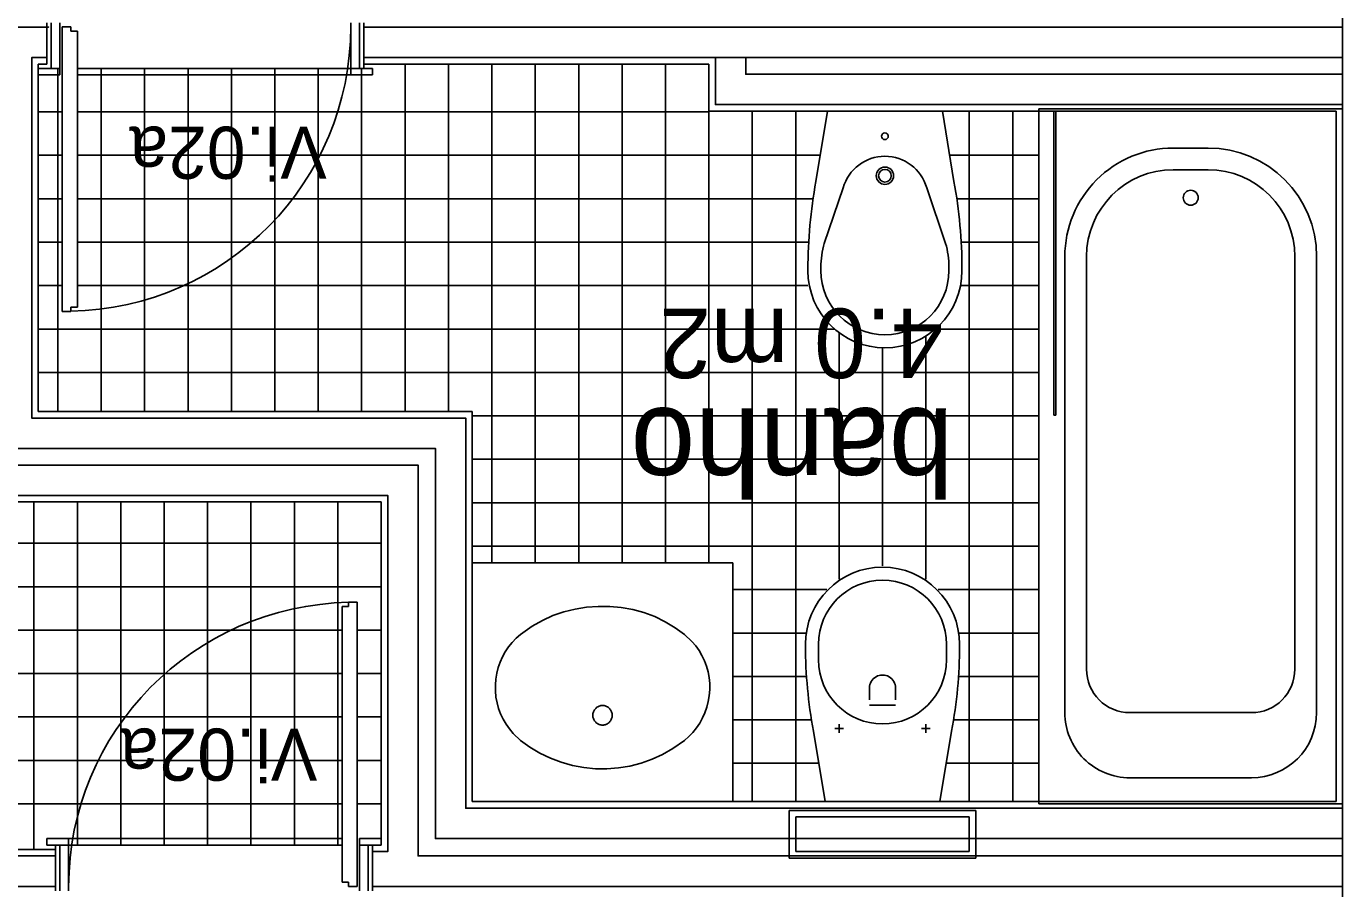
# Model space of a CAD drawing. Extents: x 1278 to 1356, y -253.7 to -224.
# Drawn here: x 1326.169 to 1329.202, y -240.419 to -238.434 of the extents above; entities that cross this region are included whole.
import ezdxf

# ---------------------------------------------------------------- set-up
doc = ezdxf.new("R2010")
doc.units = 0
for name, color, linetype in [('Level 1', 7, 'Continuous'), ('Level 10', 7, 'Continuous'), ('Level 11', 7, 'Continuous'), ('Level 13', 7, 'Continuous'), ('Level 2', 7, 'Continuous'), ('Level 36', 7, 'Continuous'), ('Level 4', 7, 'Continuous'), ('Level 40', 7, 'Continuous'), ('Level 60', 7, 'Continuous'), ('Level 65', 7, 'Continuous'), ('Level 66', 7, 'Continuous'), ('Level 67', 7, 'Continuous')]:
    doc.layers.add(name, color=color, linetype=linetype)

msp = doc.modelspace()

# ---------------------------------------------------------------- linework, layer by layer
at = {"layer": 'Level 1'}
for p, q in [((1326.2168, -238.5207), (1326.2168, -238.4257)), ((1326.9468, -238.5307), (1326.9468, -238.4257)), ((1326.2168, -238.4357), (1326.1318, -238.4357)), ((1329.2018, -238.4357), (1326.9468, -238.4357)), ((1326.1818, -239.3357), (1326.1818, -238.5057)), ((1326.1818, -238.5057), (1326.2168, -238.5057)), ((1327.7568, -238.5057), (1326.9468, -238.5057)), ((1329.2018, -238.5057), (1327.8268, -238.5057)), ((1327.1818, -239.3357), (1326.1818, -239.3357)), ((1327.1818, -240.234), (1327.1818, -239.3357)), ((1327.1118, -239.4057), (1326.1118, -239.4057)), ((1327.1118, -240.304), (1327.1118, -239.4057)), ((1326.0718, -239.444), (1327.0718, -239.444)), ((1327.0718, -239.444), (1327.0718, -240.344)), ((1326.0018, -239.514), (1327.0018, -239.514)), ((1327.0018, -239.514), (1327.0018, -240.334)), ((1326.2368, -240.319), (1326.2368, -240.424)), ((1326.9668, -240.319), (1326.9668, -240.424)), ((1327.0018, -240.334), (1326.9668, -240.334)), ((1327.0718, -240.344), (1329.2018, -240.344)), ((1326.1268, -240.414), (1326.2368, -240.414)), ((1326.9668, -240.414), (1329.2018, -240.414)), ((1329.2018, -240.414), (1329.2018, -242.034))]:
    msp.add_line(p, q, dxfattribs=at)
at = {"layer": 'Level 10'}
for p, q in [((1326.2418, -238.5307), (1326.2418, -239.3207)), ((1326.9168, -238.5307), (1326.2868, -238.5307)), ((1326.3418, -238.5307), (1326.3418, -239.3207)), ((1326.4418, -238.5307), (1326.4418, -239.3207)), ((1326.5418, -238.5307), (1326.5418, -239.3207)), ((1326.6418, -238.5307), (1326.6418, -239.3207)), ((1326.7418, -238.5307), (1326.7418, -239.3207)), ((1326.8418, -238.5307), (1326.8418, -239.3207)), ((1326.9418, -238.5307), (1326.9418, -239.3207)), ((1327.0418, -238.5207), (1327.0418, -239.3207)), ((1327.1418, -238.5207), (1327.1418, -239.3207)), ((1327.2418, -238.5207), (1327.2418, -239.669)), ((1327.3418, -238.5207), (1327.3418, -239.669)), ((1327.4418, -238.5207), (1327.4418, -239.669)), ((1327.5418, -238.5207), (1327.5418, -239.669)), ((1327.6418, -238.5207), (1327.6418, -239.669)), ((1326.1968, -238.6307), (1326.2518, -238.6307)), ((1326.2868, -238.6307), (1327.7418, -238.6307)), ((1327.7418, -238.629), (1327.7418, -239.669)), ((1327.8418, -238.629), (1327.8418, -240.219)), ((1327.9418, -238.629), (1327.9418, -240.219)), ((1328.3418, -238.629), (1328.3418, -240.219)), ((1328.4418, -238.629), (1328.4418, -240.219)), ((1326.1968, -238.7307), (1326.2518, -238.7307)), ((1326.2868, -238.7307), (1327.9984, -238.7307)), ((1328.2965, -238.7307), (1328.5018, -238.7307)), ((1326.1968, -238.8307), (1326.2518, -238.8307)), ((1326.2868, -238.8307), (1327.9819, -238.8307)), ((1328.313, -238.8307), (1328.5018, -238.8307)), ((1326.1968, -238.9307), (1326.2518, -238.9307)), ((1326.2868, -238.9307), (1327.9717, -238.9307)), ((1328.3232, -238.9307), (1328.5018, -238.9307)), ((1326.1968, -239.0307), (1326.2518, -239.0307)), ((1326.2868, -239.0307), (1327.9699, -239.0307)), ((1328.3216, -239.0307), (1328.5018, -239.0307)), ((1326.1968, -239.1307), (1328.0313, -239.1307)), ((1328.0418, -239.1391), (1328.0418, -239.7067)), ((1328.2418, -239.1468), (1328.2418, -239.7067)), ((1328.2635, -239.1307), (1328.5018, -239.1307)), ((1328.1418, -239.1739), (1328.1418, -239.6759)), ((1326.1968, -239.2307), (1328.5018, -239.2307)), ((1327.1968, -239.3307), (1328.5018, -239.3307)), ((1327.1968, -239.4307), (1328.5018, -239.4307)), ((1326.1868, -239.529), (1326.1868, -240.329)), ((1326.2868, -239.529), (1326.2868, -240.319)), ((1326.3868, -239.529), (1326.3868, -240.319)), ((1326.4868, -239.529), (1326.4868, -240.319)), ((1326.5868, -239.529), (1326.5868, -240.319)), ((1326.6868, -239.529), (1326.6868, -240.319)), ((1326.7868, -239.529), (1326.7868, -240.319)), ((1326.8868, -239.529), (1326.8868, -240.319)), ((1327.1968, -239.5307), (1328.5018, -239.5307)), ((1324.7318, -239.624), (1326.9868, -239.624)), ((1327.1968, -239.6307), (1328.5018, -239.6307)), ((1325.2019, -239.724), (1326.9868, -239.724)), ((1327.7966, -239.7307), (1328.0135, -239.7307)), ((1328.2701, -239.7307), (1328.5018, -239.7307)), ((1325.2555, -239.824), (1326.8968, -239.824)), ((1326.9318, -239.824), (1326.9868, -239.824)), ((1327.7966, -239.8307), (1327.9657, -239.8307)), ((1328.3178, -239.8307), (1328.5018, -239.8307)), ((1325.2538, -239.924), (1326.8968, -239.924)), ((1326.9318, -239.924), (1326.9868, -239.924)), ((1327.7966, -239.9307), (1327.9669, -239.9307)), ((1328.3167, -239.9307), (1328.5018, -239.9307)), ((1325.243, -240.024), (1326.8968, -240.024)), ((1326.9318, -240.024), (1326.9868, -240.024)), ((1327.7966, -240.0307), (1327.9787, -240.0307)), ((1328.3049, -240.0307), (1328.5018, -240.0307)), ((1325.2264, -240.124), (1326.8968, -240.124)), ((1326.9318, -240.124), (1326.9868, -240.124)), ((1327.7966, -240.1307), (1327.9955, -240.1307)), ((1328.2881, -240.1307), (1328.5018, -240.1307)), ((1325.4868, -240.224), (1326.8968, -240.224)), ((1326.9318, -240.224), (1326.9868, -240.224)), ((1326.2668, -240.319), (1326.8968, -240.319))]:
    msp.add_line(p, q, dxfattribs=at)
at = {"layer": 'Level 11'}
for p, q in [((1328.0151, -238.629), (1327.9885, -238.791)), ((1328.0151, -238.629), (1328.2797, -238.629)), ((1328.2797, -238.629), (1328.3064, -238.791)), ((1329.2018, -238.624), (1328.5018, -238.624)), ((1328.5018, -238.624), (1328.5018, -240.224)), ((1329.2018, -238.624), (1329.2018, -240.224)), ((1328.8918, -238.714), (1328.8118, -238.714)), ((1328.8918, -238.764), (1328.8118, -238.764)), ((1328.0076, -238.9335), (1328.0513, -238.8055)), ((1328.2872, -238.9335), (1328.2436, -238.8055)), ((1328.5618, -238.964), (1328.5618, -240.014)), ((1328.6118, -238.964), (1328.6118, -239.914)), ((1329.0918, -238.964), (1329.0918, -239.914)), ((1329.1418, -238.964), (1329.1418, -240.014)), ((1327.9699, -238.9931), (1327.9699, -238.9968)), ((1327.9999, -238.9965), (1327.9999, -238.9884)), ((1328.2949, -238.9965), (1328.2949, -238.9884)), ((1328.3249, -238.9931), (1328.3249, -238.9968)), ((1327.3825, -239.7905), (1327.3582, -239.8017)), ((1327.4077, -239.7816), (1327.3825, -239.7905)), ((1327.4337, -239.7759), (1327.4077, -239.7816)), ((1327.46, -239.7715), (1327.4337, -239.7759)), ((1327.4866, -239.7694), (1327.46, -239.7715)), ((1327.5133, -239.7697), (1327.4866, -239.7694)), ((1327.5398, -239.7723), (1327.5133, -239.7697)), ((1327.5662, -239.7763), (1327.5398, -239.7723)), ((1327.5919, -239.7835), (1327.5662, -239.7763)), ((1327.6169, -239.793), (1327.5919, -239.7835)), ((1327.6409, -239.8047), (1327.6169, -239.793)), ((1327.335, -239.8149), (1327.3079, -239.8341)), ((1327.3582, -239.8017), (1327.335, -239.8149)), ((1327.6639, -239.8184), (1327.6409, -239.8047)), ((1327.6856, -239.8341), (1327.6639, -239.8184)), ((1327.2886, -239.8524), (1327.2802, -239.8628)), ((1327.2979, -239.8428), (1327.2886, -239.8524)), ((1327.3079, -239.8341), (1327.2979, -239.8428)), ((1327.7028, -239.85), (1327.6856, -239.8341)), ((1327.7114, -239.8602), (1327.7028, -239.85)), ((1327.2727, -239.8738), (1327.2662, -239.8855)), ((1327.2802, -239.8628), (1327.2727, -239.8738)), ((1327.7191, -239.8711), (1327.7114, -239.8602)), ((1327.7259, -239.8827), (1327.7191, -239.8711)), ((1327.7316, -239.8948), (1327.7259, -239.8827)), ((1327.9643, -239.8598), (1327.9643, -239.8562)), ((1327.9943, -239.8565), (1327.9943, -239.8926)), ((1328.2893, -239.8565), (1328.2893, -239.8926)), ((1328.3193, -239.8598), (1328.3193, -239.8562)), ((1327.2563, -239.9104), (1327.253, -239.9234)), ((1327.2607, -239.8977), (1327.2563, -239.9104)), ((1327.2662, -239.8855), (1327.2607, -239.8977)), ((1327.7363, -239.9073), (1327.7316, -239.8948)), ((1327.7398, -239.9202), (1327.7363, -239.9073)), ((1327.2508, -239.9366), (1327.2498, -239.95)), ((1327.253, -239.9234), (1327.2508, -239.9366)), ((1327.7423, -239.9334), (1327.7398, -239.9202)), ((1327.7436, -239.9468), (1327.7423, -239.9334)), ((1327.2498, -239.95), (1327.2499, -239.9638)), ((1327.2499, -239.9638), (1327.2512, -239.9784)), ((1327.7405, -239.9885), (1327.7427, -239.9753)), ((1327.7427, -239.9753), (1327.7437, -239.9606)), ((1327.7437, -239.9606), (1327.7436, -239.9468)), ((1328.1118, -239.9845), (1328.1118, -239.9572)), ((1328.1718, -239.9845), (1328.1718, -239.9573)), ((1327.2512, -239.9784), (1327.2537, -239.9916)), ((1327.2537, -239.9916), (1327.2572, -240.0045)), ((1327.2572, -240.0045), (1327.2619, -240.0171)), ((1327.481, -240.0042), (1327.4797, -240.0057)), ((1327.4824, -240.0029), (1327.481, -240.0042)), ((1327.484, -240.0017), (1327.4824, -240.0029)), ((1327.4856, -240.0006), (1327.484, -240.0017)), ((1327.4873, -239.9997), (1327.4856, -240.0006)), ((1327.4891, -239.999), (1327.4873, -239.9997)), ((1327.491, -239.9984), (1327.4891, -239.999)), ((1327.4929, -239.9979), (1327.491, -239.9984)), ((1327.4948, -239.9977), (1327.4929, -239.9979)), ((1327.4968, -239.9976), (1327.4948, -239.9977)), ((1327.4987, -239.9977), (1327.4968, -239.9976)), ((1327.5006, -239.9979), (1327.4987, -239.9977)), ((1327.5025, -239.9984), (1327.5006, -239.9979)), ((1327.5044, -239.999), (1327.5025, -239.9984)), ((1327.5062, -239.9997), (1327.5044, -239.999)), ((1327.5079, -240.0006), (1327.5062, -239.9997)), ((1327.5095, -240.0017), (1327.5079, -240.0006)), ((1327.5111, -240.0029), (1327.5095, -240.0017)), ((1327.5125, -240.0042), (1327.5111, -240.0029)), ((1327.5138, -240.0057), (1327.5125, -240.0042)), ((1327.7328, -240.0141), (1327.7372, -240.0015)), ((1327.7372, -240.0015), (1327.7405, -239.9885)), ((1328.1718, -239.9968), (1328.1118, -239.9968)), ((1327.2619, -240.0171), (1327.2676, -240.0292)), ((1327.2676, -240.0292), (1327.2744, -240.0407)), ((1327.4745, -240.0182), (1327.4744, -240.0202)), ((1327.4744, -240.0202), (1327.4745, -240.0221)), ((1327.4748, -240.0162), (1327.4745, -240.0182)), ((1327.4745, -240.0221), (1327.4748, -240.0241)), ((1327.4752, -240.0143), (1327.4748, -240.0162)), ((1327.4748, -240.0241), (1327.4752, -240.026)), ((1327.4758, -240.0124), (1327.4752, -240.0143)), ((1327.4752, -240.026), (1327.4758, -240.0279)), ((1327.4765, -240.0106), (1327.4758, -240.0124)), ((1327.4758, -240.0279), (1327.4765, -240.0297)), ((1327.4774, -240.0089), (1327.4765, -240.0106)), ((1327.4765, -240.0297), (1327.4774, -240.0314)), ((1327.4785, -240.0072), (1327.4774, -240.0089)), ((1327.4774, -240.0314), (1327.4785, -240.0331)), ((1327.4797, -240.0057), (1327.4785, -240.0072)), ((1327.4785, -240.0331), (1327.4797, -240.0347)), ((1327.4797, -240.0347), (1327.481, -240.0361)), ((1327.5125, -240.0361), (1327.5138, -240.0347)), ((1327.515, -240.0072), (1327.5138, -240.0057)), ((1327.5138, -240.0347), (1327.515, -240.0331)), ((1327.5161, -240.0089), (1327.515, -240.0072)), ((1327.515, -240.0331), (1327.5161, -240.0314)), ((1327.517, -240.0106), (1327.5161, -240.0089)), ((1327.5161, -240.0314), (1327.517, -240.0297)), ((1327.5177, -240.0124), (1327.517, -240.0106)), ((1327.517, -240.0297), (1327.5177, -240.0279)), ((1327.5183, -240.0143), (1327.5177, -240.0124)), ((1327.5177, -240.0279), (1327.5183, -240.026)), ((1327.5187, -240.0162), (1327.5183, -240.0143)), ((1327.5183, -240.026), (1327.5187, -240.0241)), ((1327.519, -240.0182), (1327.5187, -240.0162)), ((1327.5187, -240.0241), (1327.519, -240.0221)), ((1327.5191, -240.0202), (1327.519, -240.0182)), ((1327.519, -240.0221), (1327.5191, -240.0202)), ((1327.7208, -240.038), (1327.7273, -240.0263)), ((1327.7273, -240.0263), (1327.7328, -240.0141)), ((1328.9918, -240.014), (1328.7118, -240.014)), ((1327.2744, -240.0407), (1327.2821, -240.0516)), ((1327.2821, -240.0516), (1327.2907, -240.0618)), ((1327.2907, -240.0618), (1327.3079, -240.0778)), ((1327.481, -240.0361), (1327.4824, -240.0374)), ((1327.4824, -240.0374), (1327.484, -240.0386)), ((1327.484, -240.0386), (1327.4856, -240.0397)), ((1327.4856, -240.0397), (1327.4873, -240.0406)), ((1327.4873, -240.0406), (1327.4891, -240.0414)), ((1327.4891, -240.0414), (1327.491, -240.042)), ((1327.491, -240.042), (1327.4929, -240.0424)), ((1327.4929, -240.0424), (1327.4948, -240.0426)), ((1327.4948, -240.0426), (1327.4968, -240.0427)), ((1327.4968, -240.0427), (1327.4987, -240.0426)), ((1327.4987, -240.0426), (1327.5006, -240.0424)), ((1327.5006, -240.0424), (1327.5025, -240.042)), ((1327.5025, -240.042), (1327.5044, -240.0414)), ((1327.5044, -240.0414), (1327.5062, -240.0406)), ((1327.5062, -240.0406), (1327.5079, -240.0397)), ((1327.5079, -240.0397), (1327.5095, -240.0386)), ((1327.5095, -240.0386), (1327.5111, -240.0374)), ((1327.5111, -240.0374), (1327.5125, -240.0361)), ((1327.6956, -240.069), (1327.7049, -240.0595)), ((1327.7049, -240.0595), (1327.7133, -240.0491)), ((1327.7133, -240.0491), (1327.7208, -240.038)), ((1328.0095, -240.219), (1327.9828, -240.0569)), ((1328.0518, -240.0508), (1328.0318, -240.0508)), ((1328.0418, -240.0608), (1328.0418, -240.0408)), ((1328.2518, -240.0508), (1328.2318, -240.0508)), ((1328.2418, -240.0608), (1328.2418, -240.0408)), ((1328.2741, -240.219), (1328.3008, -240.0569)), ((1327.3079, -240.0778), (1327.3296, -240.0935)), ((1327.3296, -240.0935), (1327.3526, -240.1072)), ((1327.6585, -240.0969), (1327.6856, -240.0778)), ((1327.6856, -240.0778), (1327.6956, -240.069)), ((1327.3526, -240.1072), (1327.3766, -240.1189)), ((1327.3766, -240.1189), (1327.4016, -240.1284)), ((1327.5858, -240.1303), (1327.611, -240.1213)), ((1327.611, -240.1213), (1327.6353, -240.1102)), ((1327.6353, -240.1102), (1327.6585, -240.0969)), ((1327.4016, -240.1284), (1327.4275, -240.1356)), ((1327.4275, -240.1356), (1327.4537, -240.1406)), ((1327.4537, -240.1406), (1327.4802, -240.1432)), ((1327.4802, -240.1432), (1327.5069, -240.1435)), ((1327.5069, -240.1435), (1327.5335, -240.1414)), ((1327.5335, -240.1414), (1327.56, -240.137)), ((1327.56, -240.137), (1327.5858, -240.1303)), ((1328.9918, -240.164), (1328.7118, -240.164)), ((1327.9268, -240.239), (1327.9268, -240.349)), ((1327.9268, -240.239), (1328.3568, -240.239)), ((1328.2741, -240.219), (1328.0095, -240.219)), ((1328.3568, -240.239), (1328.3568, -240.349)), ((1329.2018, -240.224), (1328.5018, -240.224)), ((1327.9418, -240.254), (1328.3418, -240.254)), ((1327.9418, -240.254), (1327.9418, -240.334)), ((1328.3418, -240.254), (1328.3418, -240.334)), ((1327.9418, -240.334), (1328.3418, -240.334)), ((1327.9268, -240.349), (1328.3568, -240.349))]:
    msp.add_line(p, q, dxfattribs=at)
for centre, radius in [((1328.1474, -238.687), 0.00766), ((1328.1474, -238.7778), 0.02), ((1328.1474, -238.7778), 0.0146), ((1328.8518, -238.8284), 0.0173)]:
    msp.add_circle(centre, radius, dxfattribs=at)
for centre, radius, start, end in [((1328.8118, -238.964), 0.25, 89.9999, 180), ((1328.8918, -238.964), 0.25, 0.0001, 90.0001), ((1328.1474, -238.833), 0.1, 15.9317, 164.1953), ((1328.8118, -238.964), 0.2, 90, 180), ((1328.8918, -238.964), 0.2, 360, 90), ((1328.1999, -238.9884), 0.2, 164.0693, 180.0006), ((1328.0949, -238.9884), 0.2, 0.0017, 15.9319), ((1328.1474, -238.9965), 0.1775, 180.0002, 359.9999), ((1328.1474, -238.9965), 0.1475, 180.0002, 359.9999), ((1328.1418, -239.8565), 0.1775, 0.0002, 179.9999), ((1328.1418, -239.8565), 0.1475, 0.0002, 179.9999), ((1328.1418, -239.8926), 0.1475, 180.0002, 359.9999), ((1328.7118, -239.914), 0.1, 180.0001, 269.9999), ((1328.9918, -239.914), 0.1, 270, 0), ((1328.1418, -239.9574), 0.03, 359.9995, 180.0013), ((1328.7118, -240.014), 0.15, 179.9998, 270.0001), ((1328.9918, -240.014), 0.15, 270, 0)]:
    msp.add_arc(centre, radius, start, end, dxfattribs=at)
for centre, major_axis, ratio, start_param, end_param in [((1329.3699, -238.9931), (-1.4, 0), 0.88995, 6.120269, 6.283187), ((1326.9249, -238.9931), (1.4, 0), 0.88995, 6.283183, 6.446102), ((1329.3643, -239.8598), (-1.4, 0), 0.867931, 6.283184, 6.446103), ((1326.9193, -239.8598), (1.4, 0), 0.867931, 6.120269, 6.283188)]:
    msp.add_ellipse(centre, major_axis=major_axis, ratio=ratio, start_param=start_param, end_param=end_param, dxfattribs=at)
at = {"layer": 'Level 13'}
for p, q in [((1326.2268, -238.5307), (1326.2268, -238.4257)), ((1326.2468, -238.4257), (1326.2468, -238.5307)), ((1326.9168, -238.4257), (1326.9168, -238.5307)), ((1326.9368, -238.5307), (1326.9368, -238.4257)), ((1326.2518, -239.0901), (1326.2518, -238.4351)), ((1326.2518, -238.4351), (1326.2718, -238.4351)), ((1326.2718, -238.4351), (1326.2718, -238.4451)), ((1326.2718, -238.4451), (1326.2868, -238.4451)), ((1326.2868, -238.4451), (1326.2868, -239.0801)), ((1326.2468, -238.5307), (1326.1968, -238.5307)), ((1326.1968, -238.5457), (1326.2468, -238.5457)), ((1326.2468, -238.5307), (1326.2268, -238.5307)), ((1326.2468, -238.5457), (1326.2468, -238.5307)), ((1326.9168, -238.5457), (1326.9168, -238.5307)), ((1326.9168, -238.5307), (1326.9368, -238.5307)), ((1326.9168, -238.5307), (1326.9668, -238.5307)), ((1326.9668, -238.5457), (1326.9168, -238.5457)), ((1326.9668, -238.5307), (1326.9668, -238.5457)), ((1326.2718, -239.0901), (1326.2518, -239.0901)), ((1326.2718, -239.0801), (1326.2718, -239.0898)), ((1326.2868, -239.0801), (1326.2718, -239.0801)), ((1326.9118, -239.7597), (1326.9318, -239.7597)), ((1326.9118, -239.7697), (1326.9118, -239.76)), ((1326.9318, -239.7597), (1326.9318, -240.4147)), ((1326.8968, -240.4047), (1326.8968, -239.7697)), ((1326.8968, -239.7697), (1326.9118, -239.7697)), ((1326.2168, -240.304), (1326.2668, -240.304)), ((1326.2168, -240.319), (1326.2168, -240.304)), ((1326.2668, -240.304), (1326.2668, -240.319)), ((1326.9868, -240.304), (1326.9368, -240.304)), ((1326.9368, -240.304), (1326.9368, -240.319)), ((1326.2668, -240.319), (1326.2168, -240.319)), ((1326.2468, -240.319), (1326.2468, -240.424)), ((1326.2668, -240.319), (1326.2468, -240.319)), ((1326.2668, -240.424), (1326.2668, -240.319)), ((1326.9368, -240.424), (1326.9368, -240.319)), ((1326.9368, -240.319), (1326.9568, -240.319)), ((1326.9368, -240.319), (1326.9868, -240.319)), ((1326.9568, -240.319), (1326.9568, -240.424)), ((1326.9118, -240.4047), (1326.8968, -240.4047)), ((1326.9118, -240.4147), (1326.9118, -240.4047)), ((1326.9318, -240.4147), (1326.9118, -240.4147))]:
    msp.add_line(p, q, dxfattribs=at)
at = {"layer": 'Level 2'}
for p, q in [((1327.7966, -239.669), (1327.1968, -239.669)), ((1327.1968, -239.669), (1327.1968, -240.219)), ((1327.7966, -240.219), (1327.7966, -239.669))]:
    msp.add_line(p, q, dxfattribs=at)
at = {"layer": 'Level 36'}
for p, q in [((1328.5362, -238.629), (1328.5362, -239.329)), ((1328.5412, -238.629), (1328.5412, -239.329)), ((1328.5362, -239.329), (1328.5412, -239.329))]:
    msp.add_line(p, q, dxfattribs=at)
at = {"layer": 'Level 4'}
for p, q in [((1326.9168, -238.5457), (1326.2868, -238.5457)), ((1326.2668, -240.304), (1326.8968, -240.304))]:
    msp.add_line(p, q, dxfattribs=at)
for centre, major_axis in [((1326.2581, -238.435), (-0.6586, 0)), ((1326.9254, -240.4147), (0.6586, 0))]:
    msp.add_ellipse(centre, major_axis=major_axis, ratio=0.994279, start_param=1.591512, end_param=3.141593, dxfattribs=at)
at = {"layer": 'Level 65'}
for p, q in [((1326.1968, -239.3207), (1326.1968, -238.5207)), ((1326.1968, -238.5207), (1326.2168, -238.5207)), ((1326.9468, -238.5207), (1327.7418, -238.5207)), ((1327.7418, -238.629), (1327.7418, -238.5207)), ((1327.7418, -238.629), (1329.1868, -238.629)), ((1329.1868, -238.629), (1329.1868, -240.219)), ((1327.1968, -239.3207), (1326.1968, -239.3207)), ((1327.1968, -240.219), (1327.1968, -239.3207)), ((1325.9868, -239.529), (1326.9868, -239.529)), ((1326.9868, -239.529), (1326.9868, -240.319)), ((1327.1968, -240.219), (1329.1868, -240.219)), ((1326.2368, -240.329), (1325.4868, -240.329)), ((1326.9868, -240.319), (1326.9668, -240.319))]:
    msp.add_line(p, q, dxfattribs=at)
at = {"layer": 'Level 66'}
for p, q in [((1329.2018, -236.8157), (1329.2018, -238.4357)), ((1327.7568, -238.614), (1327.7568, -238.5057)), ((1327.8268, -238.544), (1327.8268, -238.5057)), ((1329.2018, -238.5057), (1329.2018, -238.544)), ((1327.8268, -238.544), (1329.2018, -238.544)), ((1327.7568, -238.614), (1329.2018, -238.614)), ((1329.2018, -238.614), (1329.2018, -240.234)), ((1327.1818, -240.234), (1329.2018, -240.234)), ((1327.1118, -240.304), (1329.2018, -240.304)), ((1329.2017, -240.304), (1329.2018, -240.344)), ((1325.4718, -240.344), (1326.2368, -240.344))]:
    msp.add_line(p, q, dxfattribs=at)
at = {"layer": 'Level 67'}
for points in [[(1329.2017, -240.234), (1329.2017, -240.304), (1327.1117, -240.304), (1327.1117, -239.4057), (1326.1117, -239.4057), (1326.1117, -238.5057), (1324.9517, -238.5057), (1324.9517, -238.244), (1324.0317, -238.244), (1324.0317, -238.174), (1325.0225, -238.174), (1325.0225, -238.4357), (1326.0517, -238.4357), (1326.0517, -236.6557), (1326.1317, -236.6557), (1326.1317, -238.4357), (1326.2205, -238.4357), (1326.2167, -238.4357), (1326.2167, -238.5057), (1326.1817, -238.5057), (1326.1817, -239.3357), (1327.1817, -239.3357), (1327.1817, -240.234), (1329.2017, -240.234)], [(1329.2018, -242.1713), (1329.2718, -242.1713), (1329.2718, -236.7713), (1329.2018, -236.7713)], [(1329.2018, -238.4357), (1329.2018, -238.5057), (1326.9468, -238.5057), (1326.9468, -238.4357)], [(1327.8268, -238.5057), (1327.8268, -238.544), (1329.2018, -238.544), (1329.2018, -238.614), (1327.7568, -238.614), (1327.7568, -238.5057)], [(1329.2018, -240.414), (1326.9668, -240.414), (1326.9668, -240.334), (1327.0018, -240.334), (1327.0018, -239.514), (1326.0018, -239.514), (1326.0018, -238.614), (1324.0317, -238.614), (1324.0318, -238.544), (1326.0718, -238.544), (1326.0718, -239.444), (1327.0718, -239.444), (1327.0718, -240.344), (1329.2018, -240.344)], [(1326.2368, -240.414), (1325.0218, -240.414), (1325.0218, -240.344), (1326.2368, -240.344)]]:
    msp.add_lwpolyline(points, close=True, dxfattribs=at)

# ---------------------------------------------------------------- texts
at = {"layer": 'Level 40'}
for p in [(1326.8615, -238.6648), (1326.8397, -240.0507)]:
    msp.add_text('Vi.02a', height=0.12, rotation=180, dxfattribs=at).set_placement(p)
at = {"layer": 'Level 60'}
for s, height, p in [('4.0 m2', 0.16, (1328.2818, -239.0837)), ('banho', 0.2, (1328.3052, -239.3132))]:
    msp.add_text(s, height=height, rotation=180, dxfattribs=at).set_placement(p)

doc.saveas('drawing.dxf')
